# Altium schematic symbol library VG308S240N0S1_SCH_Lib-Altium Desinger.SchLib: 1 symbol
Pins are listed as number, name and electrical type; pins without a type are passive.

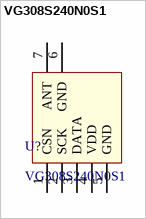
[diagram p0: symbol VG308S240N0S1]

## VG308S240N0S1
designator U?
pins: 1 CSN, 2 SCK, 3 DATA, 4 VDD, 5 GND, 6 GND, 7 ANT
